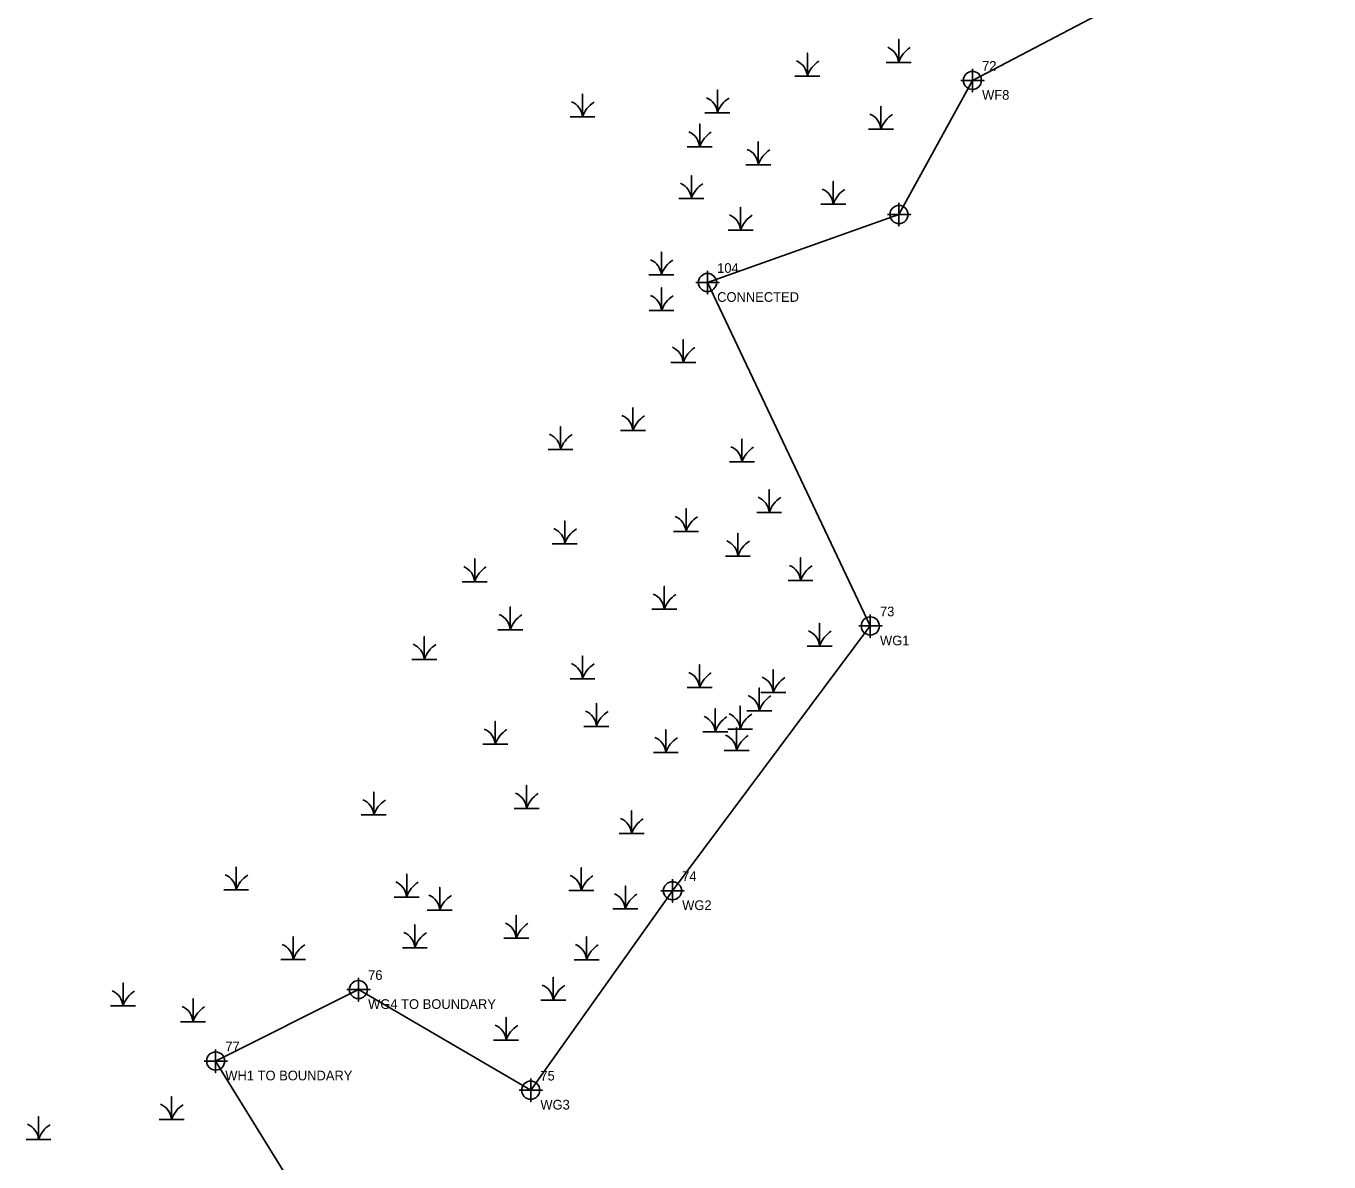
# Model space of a CAD drawing. Extents: x 2189822 to 2191198, y 387253 to 388663.
# Drawn here: x 2189853.6 to 2190190.6, y 387539.5 to 387833.3 of the extents above; entities that cross this region are included whole.
import ezdxf

# ---------------------------------------------------------------- set-up
doc = ezdxf.new("R2010")
doc.units = 0
for name, color, linetype in [('Structure020030_Alleghany', 7, 'Continuous'), ('Structure040008_Ashe', 7, 'Continuous'), ('Structure090007_Brunswick', 7, 'Continuous'), ('Structure620024_Moore', 7, 'Continuous'), ('Structure780124_Rockingham', 7, 'Continuous')]:
    doc.layers.add(name, color=color, linetype=linetype)

msp = doc.modelspace()

# ---------------------------------------------------------------- linework, layer by layer
at = {"layer": 'Structure020030_Alleghany'}
for points in [[(2190098.41, 387822.25), (2190098.41, 387816.25), (2190098.41, 387819.25), (2190101.41, 387819.25), (2190095.41, 387819.25)], [(2190079.41, 387787.56), (2190079.41, 387781.56), (2190079.41, 387784.56), (2190082.41, 387784.56), (2190076.41, 387784.56)], [(2190029.88, 387769.97), (2190029.88, 387763.97), (2190029.88, 387766.97), (2190032.88, 387766.97), (2190026.88, 387766.97)], [(2190072, 387681.13), (2190072, 387675.13), (2190072, 387678.13), (2190075, 387678.13), (2190069, 387678.13)], [(2190020.83, 387612.65), (2190020.83, 387606.65), (2190020.83, 387609.65), (2190023.83, 387609.65), (2190017.83, 387609.65)], [(2189939.6, 387587.08), (2189939.6, 387581.08), (2189939.6, 387584.08), (2189942.6, 387584.08), (2189936.6, 387584.08)], [(2189902.66, 387568.6), (2189902.66, 387562.6), (2189902.66, 387565.6), (2189905.66, 387565.6), (2189899.66, 387565.6)], [(2189984.15, 387561.06), (2189984.15, 387555.06), (2189984.15, 387558.06), (2189987.15, 387558.06), (2189981.15, 387558.06)]]:
    msp.add_lwpolyline(points, dxfattribs=at)
for centre in [(2190098.41, 387819.25), (2190079.41, 387784.56), (2190029.88, 387766.97), (2190072, 387678.13), (2190020.83, 387609.65), (2189939.6, 387584.08), (2189902.66, 387565.6), (2189984.15, 387558.06)]:
    msp.add_circle(centre, 2.34, dxfattribs=at)
at = {"layer": 'Structure620024_Moore'}
for points in [[(2190311.6, 387912.32), (2190282.87, 387902.15), (2190276.9, 387926.61), (2190246.66, 387930.44), (2190212.31, 387905.81), (2190187.82, 387866.13), (2190141.4, 387841.78), (2190098.41, 387819.25)], [(2190098.41, 387819.25), (2190079.41, 387784.56), (2190029.88, 387766.97)], [(2190029.88, 387766.97), (2190072, 387678.13)], [(2190072, 387678.13), (2190020.83, 387609.65), (2189984.15, 387558.06), (2189939.6, 387584.08), (2189902.66, 387565.6), (2189935.31, 387512.67), (2189942.75, 387482.02), (2189939.21, 387443.81), (2189912.73, 387459.73), (2189904.28, 387465.08), (2189897.31, 387471.8), (2189873.08, 387504.47), (2189858.16, 387512.76)]]:
    msp.add_lwpolyline(points, dxfattribs=at)
at = {"layer": 'Structure780124_Rockingham'}
for p, q in [((2190079.33, 387826.58), (2190079.33, 387826.58)), ((2190055.71, 387823.05), (2190055.71, 387823.05)), ((2190032.44, 387813.53), (2190032.44, 387813.53)), ((2189997.54, 387812.47), (2189997.54, 387812.47)), ((2190074.74, 387809.3), (2190074.74, 387809.3)), ((2190027.86, 387804.71), (2190027.86, 387804.71)), ((2190043.02, 387800.13), (2190043.02, 387800.13)), ((2190025.71, 387791.38), (2190025.71, 387791.38)), ((2190062.41, 387789.9), (2190062.41, 387789.9)), ((2190038.43, 387783.19), (2190038.43, 387783.19)), ((2190017.95, 387771.62), (2190017.95, 387771.62)), ((2190017.99, 387762.38), (2190017.99, 387762.38)), ((2190023.63, 387748.98), (2190023.63, 387748.98)), ((2190010.58, 387731.34), (2190010.58, 387731.34)), ((2189991.86, 387726.47), (2189991.86, 387726.47)), ((2190038.79, 387723.23), (2190038.79, 387723.23)), ((2190045.84, 387710.17), (2190045.84, 387710.17)), ((2189992.96, 387702.06), (2189992.96, 387702.06)), ((2190024.33, 387705.24), (2190024.33, 387705.24)), ((2190037.73, 387698.89), (2190037.73, 387698.89)), ((2189969.65, 387692.25), (2189969.65, 387692.25)), ((2190053.95, 387692.54), (2190053.95, 387692.54)), ((2190018.69, 387685.13), (2190018.69, 387685.13)), ((2189978.86, 387679.84), (2189978.86, 387679.84)), ((2190058.88, 387675.6), (2190058.88, 387675.6)), ((2189956.61, 387672.15), (2189956.61, 387672.15)), ((2189997.54, 387667.14), (2189997.54, 387667.14)), ((2190027.85, 387664.86), (2190027.85, 387664.86)), ((2190046.89, 387663.61), (2190046.89, 387663.61)), ((2190043.28, 387658.87), (2190043.28, 387658.87)), ((2190001.15, 387654.84), (2190001.15, 387654.84)), ((2190031.88, 387653.46), (2190031.88, 387653.46)), ((2190038.33, 387654.15), (2190038.33, 387654.15)), ((2189974.98, 387650.21), (2189974.98, 387650.21)), ((2190019.1, 387648.05), (2190019.1, 387648.05)), ((2190037.41, 387648.62), (2190037.41, 387648.62)), ((2189943.57, 387631.93), (2189943.57, 387631.93)), ((2189983.09, 387633.63), (2189983.09, 387633.63)), ((2190010.24, 387627.08), (2190010.24, 387627.08)), ((2189907.96, 387612.53), (2189907.96, 387612.53)), ((2189997.23, 387612.34), (2189997.23, 387612.34)), ((2189952.07, 387610.7), (2189952.07, 387610.7)), ((2190008.63, 387607.62), (2190008.63, 387607.62)), ((2189960.63, 387607.27), (2189960.63, 387607.27)), ((2189954.18, 387597.6), (2189954.18, 387597.6)), ((2189980.43, 387600.01), (2189980.43, 387600.01)), ((2189922.72, 387594.51), (2189922.72, 387594.51)), ((2189998.61, 387594.49), (2189998.61, 387594.49)), ((2189989.98, 387584), (2189989.98, 387584)), ((2189878.7, 387582.55), (2189878.7, 387582.55)), ((2189896.81, 387578.46), (2189896.81, 387578.46)), ((2189977.78, 387573.64), (2189977.78, 387573.64)), ((2189891.26, 387553.15), (2189891.26, 387553.15)), ((2189856.85, 387547.98), (2189856.85, 387547.98))]:
    msp.add_line(p, q, dxfattribs=at)
for points in [[(2190076.1, 387823.91), (2190079.33, 387823.91), (2190079.33, 387829.83), (2190079.33, 387823.91), (2190082.55, 387823.91)], [(2190052.48, 387820.38), (2190055.71, 387820.38), (2190055.71, 387826.3), (2190055.71, 387820.38), (2190058.93, 387820.38)], [(2190029.22, 387810.86), (2190032.44, 387810.86), (2190032.44, 387816.77), (2190032.44, 387810.86), (2190035.67, 387810.86)], [(2189994.32, 387809.8), (2189997.54, 387809.8), (2189997.54, 387815.72), (2189997.54, 387809.8), (2190000.77, 387809.8)], [(2190071.52, 387806.62), (2190074.75, 387806.62), (2190074.75, 387812.54), (2190074.75, 387806.62), (2190077.97, 387806.62)], [(2190024.63, 387802.04), (2190027.86, 387802.04), (2190027.86, 387807.95), (2190027.86, 387802.04), (2190031.08, 387802.04)], [(2190039.79, 387797.45), (2190043.02, 387797.45), (2190043.02, 387803.37), (2190043.02, 387797.45), (2190046.24, 387797.45)], [(2190022.48, 387788.7), (2190025.71, 387788.7), (2190025.71, 387794.62), (2190025.71, 387788.7), (2190028.93, 387788.7)], [(2190059.18, 387787.22), (2190062.41, 387787.22), (2190062.41, 387793.14), (2190062.41, 387787.22), (2190065.63, 387787.22)], [(2190035.21, 387780.52), (2190038.43, 387780.52), (2190038.43, 387786.44), (2190038.43, 387780.52), (2190041.66, 387780.52)], [(2190014.73, 387768.95), (2190017.95, 387768.95), (2190017.95, 387774.86), (2190017.95, 387768.95), (2190021.18, 387768.95)], [(2190014.76, 387759.71), (2190017.99, 387759.71), (2190017.99, 387765.62), (2190017.99, 387759.71), (2190021.21, 387759.71)], [(2190020.4, 387746.3), (2190023.63, 387746.3), (2190023.63, 387752.22), (2190023.63, 387746.3), (2190026.85, 387746.3)], [(2190007.36, 387728.66), (2190010.59, 387728.66), (2190010.59, 387734.58), (2190010.59, 387728.66), (2190013.81, 387728.66)], [(2189988.64, 387723.79), (2189991.86, 387723.79), (2189991.86, 387729.71), (2189991.86, 387723.79), (2189995.09, 387723.79)], [(2190035.56, 387720.55), (2190038.79, 387720.55), (2190038.79, 387726.47), (2190038.79, 387720.55), (2190042.01, 387720.55)], [(2190042.61, 387707.5), (2190045.84, 387707.5), (2190045.84, 387713.42), (2190045.84, 387707.5), (2190049.06, 387707.5)], [(2190021.11, 387702.56), (2190024.33, 387702.56), (2190024.33, 387708.48), (2190024.33, 387702.56), (2190027.56, 387702.56)], [(2189989.73, 387699.39), (2189992.96, 387699.39), (2189992.96, 387705.3), (2189992.96, 387699.39), (2189996.18, 387699.39)], [(2190034.5, 387696.21), (2190037.73, 387696.21), (2190037.73, 387702.13), (2190037.73, 387696.21), (2190040.96, 387696.21)], [(2189966.43, 387689.58), (2189969.66, 387689.58), (2189969.66, 387695.5), (2189969.66, 387689.58), (2189972.88, 387689.58)], [(2190050.72, 387689.86), (2190053.95, 387689.86), (2190053.95, 387695.78), (2190053.95, 387689.86), (2190057.17, 387689.86)], [(2190015.47, 387682.45), (2190018.69, 387682.45), (2190018.69, 387688.37), (2190018.69, 387682.45), (2190021.92, 387682.45)], [(2189975.63, 387677.16), (2189978.86, 387677.16), (2189978.86, 387683.08), (2189978.86, 387677.16), (2189982.08, 387677.16)], [(2190055.66, 387672.93), (2190058.88, 387672.93), (2190058.88, 387678.85), (2190058.88, 387672.93), (2190062.11, 387672.93)], [(2189953.39, 387669.47), (2189956.61, 387669.47), (2189956.61, 387675.39), (2189956.61, 387669.47), (2189959.84, 387669.47)], [(2189994.32, 387664.46), (2189997.54, 387664.46), (2189997.54, 387670.38), (2189997.54, 387664.46), (2190000.77, 387664.46)], [(2190024.63, 387662.19), (2190027.85, 387662.19), (2190027.85, 387668.11), (2190027.85, 387662.19), (2190031.08, 387662.19)], [(2190043.67, 387660.94), (2190046.9, 387660.94), (2190046.9, 387666.85), (2190046.9, 387660.94), (2190050.12, 387660.94)], [(2190040.05, 387656.2), (2190043.28, 387656.2), (2190043.28, 387662.12), (2190043.28, 387656.2), (2190046.5, 387656.2)], [(2189997.92, 387652.17), (2190001.15, 387652.17), (2190001.15, 387658.09), (2190001.15, 387652.17), (2190004.37, 387652.17)], [(2190028.66, 387650.79), (2190031.88, 387650.79), (2190031.88, 387656.7), (2190031.88, 387650.79), (2190035.11, 387650.79)], [(2190035.1, 387651.48), (2190038.33, 387651.48), (2190038.33, 387657.39), (2190038.33, 387651.48), (2190041.55, 387651.48)], [(2189971.75, 387647.53), (2189974.98, 387647.53), (2189974.98, 387653.45), (2189974.98, 387647.53), (2189978.21, 387647.53)], [(2190034.18, 387645.95), (2190037.41, 387645.95), (2190037.41, 387651.87), (2190037.41, 387645.95), (2190040.63, 387645.95)], [(2190015.88, 387645.37), (2190019.1, 387645.37), (2190019.1, 387651.29), (2190019.1, 387645.37), (2190022.33, 387645.37)], [(2189940.34, 387629.26), (2189943.57, 387629.26), (2189943.57, 387635.18), (2189943.57, 387629.26), (2189946.79, 387629.26)], [(2189979.86, 387630.95), (2189983.09, 387630.95), (2189983.09, 387636.87), (2189983.09, 387630.95), (2189986.31, 387630.95)], [(2190007.01, 387624.41), (2190010.24, 387624.41), (2190010.24, 387630.33), (2190010.24, 387624.41), (2190013.47, 387624.41)], [(2189904.74, 387609.86), (2189907.96, 387609.86), (2189907.96, 387615.77), (2189907.96, 387609.86), (2189911.19, 387609.86)], [(2189994.01, 387609.67), (2189997.23, 387609.67), (2189997.23, 387615.58), (2189997.23, 387609.67), (2190000.46, 387609.67)], [(2189948.84, 387608.02), (2189952.07, 387608.02), (2189952.07, 387613.94), (2189952.07, 387608.02), (2189955.29, 387608.02)], [(2189957.4, 387604.6), (2189960.63, 387604.6), (2189960.63, 387610.51), (2189960.63, 387604.6), (2189963.85, 387604.6)], [(2190005.4, 387604.94), (2190008.63, 387604.94), (2190008.63, 387610.86), (2190008.63, 387604.94), (2190011.85, 387604.94)], [(2189977.2, 387597.34), (2189980.43, 387597.34), (2189980.43, 387603.26), (2189980.43, 387597.34), (2189983.65, 387597.34)], [(2189919.49, 387591.83), (2189922.72, 387591.83), (2189922.72, 387597.75), (2189922.72, 387591.83), (2189925.94, 387591.83)], [(2189950.96, 387594.92), (2189954.18, 387594.92), (2189954.18, 387600.84), (2189954.18, 387594.92), (2189957.41, 387594.92)], [(2189995.39, 387591.81), (2189998.61, 387591.81), (2189998.61, 387597.73), (2189998.61, 387591.81), (2190001.84, 387591.81)], [(2189875.48, 387579.87), (2189878.7, 387579.87), (2189878.7, 387585.79), (2189878.7, 387579.87), (2189881.93, 387579.87)], [(2189986.76, 387581.33), (2189989.98, 387581.33), (2189989.98, 387587.25), (2189989.98, 387581.33), (2189993.21, 387581.33)], [(2189893.58, 387575.78), (2189896.81, 387575.78), (2189896.81, 387581.7), (2189896.81, 387575.78), (2189900.03, 387575.78)], [(2189974.55, 387570.96), (2189977.78, 387570.96), (2189977.78, 387576.88), (2189977.78, 387570.96), (2189981, 387570.96)], [(2189888.03, 387550.47), (2189891.26, 387550.47), (2189891.26, 387556.39), (2189891.26, 387550.47), (2189894.48, 387550.47)], [(2189853.62, 387545.3), (2189856.85, 387545.3), (2189856.85, 387551.22), (2189856.85, 387545.3), (2189860.07, 387545.3)]]:
    msp.add_lwpolyline(points, dxfattribs=at)
for centre, radius, start, end in [((2190074.73, 387823.57), 4.61, 4.1403, 67.535), ((2190086.17, 387821.63), 7.21, 122.1274, 161.6222), ((2190051.11, 387820.05), 4.61, 4.1403, 67.535), ((2190062.55, 387818.11), 7.21, 122.1274, 161.6222), ((2189992.94, 387809.46), 4.61, 4.1403, 67.535), ((2190004.38, 387807.52), 7.21, 122.1274, 161.6222), ((2190027.84, 387810.52), 4.61, 4.1403, 67.535), ((2190039.28, 387808.58), 7.21, 122.1274, 161.6222), ((2190070.15, 387806.29), 4.61, 4.1403, 67.535), ((2190081.59, 387804.35), 7.21, 122.1274, 161.6222), ((2190023.26, 387801.7), 4.61, 4.1403, 67.535), ((2190034.7, 387799.76), 7.21, 122.1274, 161.6222), ((2190038.42, 387797.12), 4.61, 4.1403, 67.535), ((2190049.86, 387795.18), 7.21, 122.1274, 161.6222), ((2190021.11, 387788.37), 4.61, 4.1403, 67.535), ((2190032.55, 387786.43), 7.21, 122.1274, 161.6222), ((2190057.81, 387786.89), 4.61, 4.1403, 67.535), ((2190069.25, 387784.95), 7.21, 122.1274, 161.6222), ((2190033.84, 387780.19), 4.61, 4.1403, 67.535), ((2190045.28, 387778.25), 7.21, 122.1274, 161.6222), ((2190013.35, 387768.61), 4.61, 4.1403, 67.535), ((2190024.79, 387766.67), 7.21, 122.1274, 161.6222), ((2190013.39, 387759.37), 4.61, 4.1403, 67.535), ((2190024.83, 387757.43), 7.21, 122.1274, 161.6222), ((2190019.03, 387745.97), 4.61, 4.1403, 67.535), ((2190030.47, 387744.03), 7.21, 122.1274, 161.6222), ((2190005.99, 387728.33), 4.61, 4.1403, 67.535), ((2190017.43, 387726.39), 7.21, 122.1274, 161.6222), ((2189987.26, 387723.46), 4.61, 4.1403, 67.535), ((2189998.71, 387721.52), 7.21, 122.1274, 161.6222), ((2190034.19, 387720.22), 4.61, 4.1403, 67.535), ((2190045.63, 387718.28), 7.21, 122.1274, 161.6222), ((2190041.24, 387707.17), 4.61, 4.1403, 67.535), ((2190052.68, 387705.23), 7.21, 122.1274, 161.6222), ((2190019.73, 387702.23), 4.61, 4.1403, 67.535), ((2190031.17, 387700.29), 7.21, 122.1274, 161.6222), ((2189988.36, 387699.05), 4.61, 4.1403, 67.535), ((2189999.8, 387697.11), 7.21, 122.1274, 161.6222), ((2190033.13, 387695.88), 4.61, 4.1403, 67.535), ((2190044.57, 387693.94), 7.21, 122.1274, 161.6222), ((2189965.06, 387689.24), 4.61, 4.1403, 67.535), ((2189976.5, 387687.31), 7.21, 122.1274, 161.6222), ((2190049.35, 387689.53), 4.61, 4.1403, 67.535), ((2190060.79, 387687.59), 7.21, 122.1274, 161.6222), ((2190014.09, 387682.12), 4.61, 4.1403, 67.535), ((2190025.53, 387680.18), 7.21, 122.1274, 161.6222), ((2189974.26, 387676.83), 4.61, 4.1403, 67.535), ((2189985.7, 387674.89), 7.21, 122.1274, 161.6222), ((2190054.28, 387672.6), 4.61, 4.1403, 67.535), ((2190065.72, 387670.66), 7.21, 122.1274, 161.6222), ((2189952.01, 387669.14), 4.61, 4.1403, 67.535), ((2189963.45, 387667.2), 7.21, 122.1274, 161.6222), ((2189992.94, 387664.13), 4.61, 4.1403, 67.535), ((2190004.38, 387662.19), 7.21, 122.1274, 161.6222), ((2190023.25, 387661.86), 4.61, 4.1403, 67.535), ((2190034.69, 387659.92), 7.21, 122.1274, 161.6222), ((2190042.3, 387660.6), 4.61, 4.1403, 67.535), ((2190053.74, 387658.66), 7.21, 122.1274, 161.6222), ((2190038.68, 387655.87), 4.61, 4.1403, 67.535), ((2190050.12, 387653.93), 7.21, 122.1274, 161.6222), ((2189996.55, 387651.84), 4.61, 4.1403, 67.535), ((2190007.99, 387649.9), 7.21, 122.1274, 161.6222), ((2190033.73, 387651.14), 4.61, 4.1403, 67.535), ((2190045.17, 387649.2), 7.21, 122.1274, 161.6222), ((2189970.38, 387647.2), 4.61, 4.1403, 67.535), ((2190027.28, 387650.45), 4.61, 4.1403, 67.535), ((2190038.72, 387648.51), 7.21, 122.1274, 161.6222), ((2189981.82, 387645.26), 7.21, 122.1274, 161.6222), ((2190014.5, 387645.04), 4.61, 4.1403, 67.535), ((2190025.94, 387643.1), 7.21, 122.1274, 161.6222), ((2190032.81, 387645.62), 4.61, 4.1403, 67.535), ((2190044.25, 387643.68), 7.21, 122.1274, 161.6222), ((2189978.49, 387630.62), 4.61, 4.1403, 67.535), ((2189989.93, 387628.68), 7.21, 122.1274, 161.6222), ((2189938.97, 387628.92), 4.61, 4.1403, 67.535), ((2189950.41, 387626.98), 7.21, 122.1274, 161.6222), ((2190005.64, 387624.08), 4.61, 4.1403, 67.535), ((2190017.08, 387622.14), 7.21, 122.1274, 161.6222), ((2189903.36, 387609.52), 4.61, 4.1403, 67.535), ((2189914.8, 387607.58), 7.21, 122.1274, 161.6222), ((2189947.47, 387607.69), 4.61, 4.1403, 67.535), ((2189958.91, 387605.75), 7.21, 122.1274, 161.6222), ((2189992.63, 387609.33), 4.61, 4.1403, 67.535), ((2190004.07, 387607.39), 7.21, 122.1274, 161.6222), ((2189956.03, 387604.26), 4.61, 4.1403, 67.535), ((2189967.47, 387602.32), 7.21, 122.1274, 161.6222), ((2190004.03, 387604.61), 4.61, 4.1403, 67.535), ((2190015.47, 387602.67), 7.21, 122.1274, 161.6222), ((2189975.83, 387597.01), 4.61, 4.1403, 67.535), ((2189987.27, 387595.07), 7.21, 122.1274, 161.6222), ((2189949.58, 387594.59), 4.61, 4.1403, 67.535), ((2189961.02, 387592.65), 7.21, 122.1274, 161.6222), ((2189918.12, 387591.5), 4.61, 4.1403, 67.535), ((2189929.56, 387589.56), 7.21, 122.1274, 161.6222), ((2189994.01, 387591.48), 4.61, 4.1403, 67.535), ((2190005.45, 387589.54), 7.21, 122.1274, 161.6222), ((2189985.38, 387581), 4.61, 4.1403, 67.535), ((2189996.82, 387579.06), 7.21, 122.1274, 161.6222), ((2189874.1, 387579.54), 4.61, 4.1403, 67.535), ((2189885.54, 387577.6), 7.21, 122.1274, 161.6222), ((2189892.21, 387575.45), 4.61, 4.1403, 67.535), ((2189903.65, 387573.51), 7.21, 122.1274, 161.6222), ((2189973.18, 387570.63), 4.61, 4.1403, 67.535), ((2189984.62, 387568.69), 7.21, 122.1274, 161.6222), ((2189886.66, 387550.14), 4.61, 4.1403, 67.535), ((2189898.1, 387548.2), 7.21, 122.1274, 161.6222), ((2189852.25, 387544.97), 4.61, 4.1403, 67.535), ((2189863.69, 387543.03), 7.21, 122.1274, 161.6222)]:
    msp.add_arc(centre, radius, start, end, dxfattribs=at)

# ---------------------------------------------------------------- texts
at = {"layer": 'Structure040008_Ashe'}
for s, p in [('72', (2190100.91, 387821.75)), ('104', (2190032.38, 387769.47)), ('73', (2190074.5, 387680.63)), ('74', (2190023.33, 387612.15)), ('76', (2189942.1, 387586.58)), ('77', (2189905.16, 387568.1)), ('75', (2189986.65, 387560.56))]:
    msp.add_text(s, height=2.5, dxfattribs=at).set_placement(p)
at = {"layer": 'Structure090007_Brunswick'}
for s, p in [('WF8', (2190100.91, 387814.25)), ('CONNECTED', (2190032.38, 387761.97)), ('WG1', (2190074.5, 387673.13)), ('WG2', (2190023.33, 387604.65)), ('WG4 TO BOUNDARY', (2189942.1, 387579.08)), ('WH1 TO BOUNDARY', (2189905.16, 387560.6)), ('WG3', (2189986.65, 387553.06))]:
    msp.add_text(s, height=2.5, dxfattribs=at).set_placement(p)

doc.saveas('drawing.dxf')
